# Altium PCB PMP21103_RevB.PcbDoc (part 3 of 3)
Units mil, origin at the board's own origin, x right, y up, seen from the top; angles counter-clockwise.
Board outline 3500 x 4000 mil, 4 copper layers (Top Layer, Signal Layer 1, Signal Layer 2, Bottom Layer), stack 61.2 mil thick; 194 components, 123 nets, 630 pads, 189 vias.
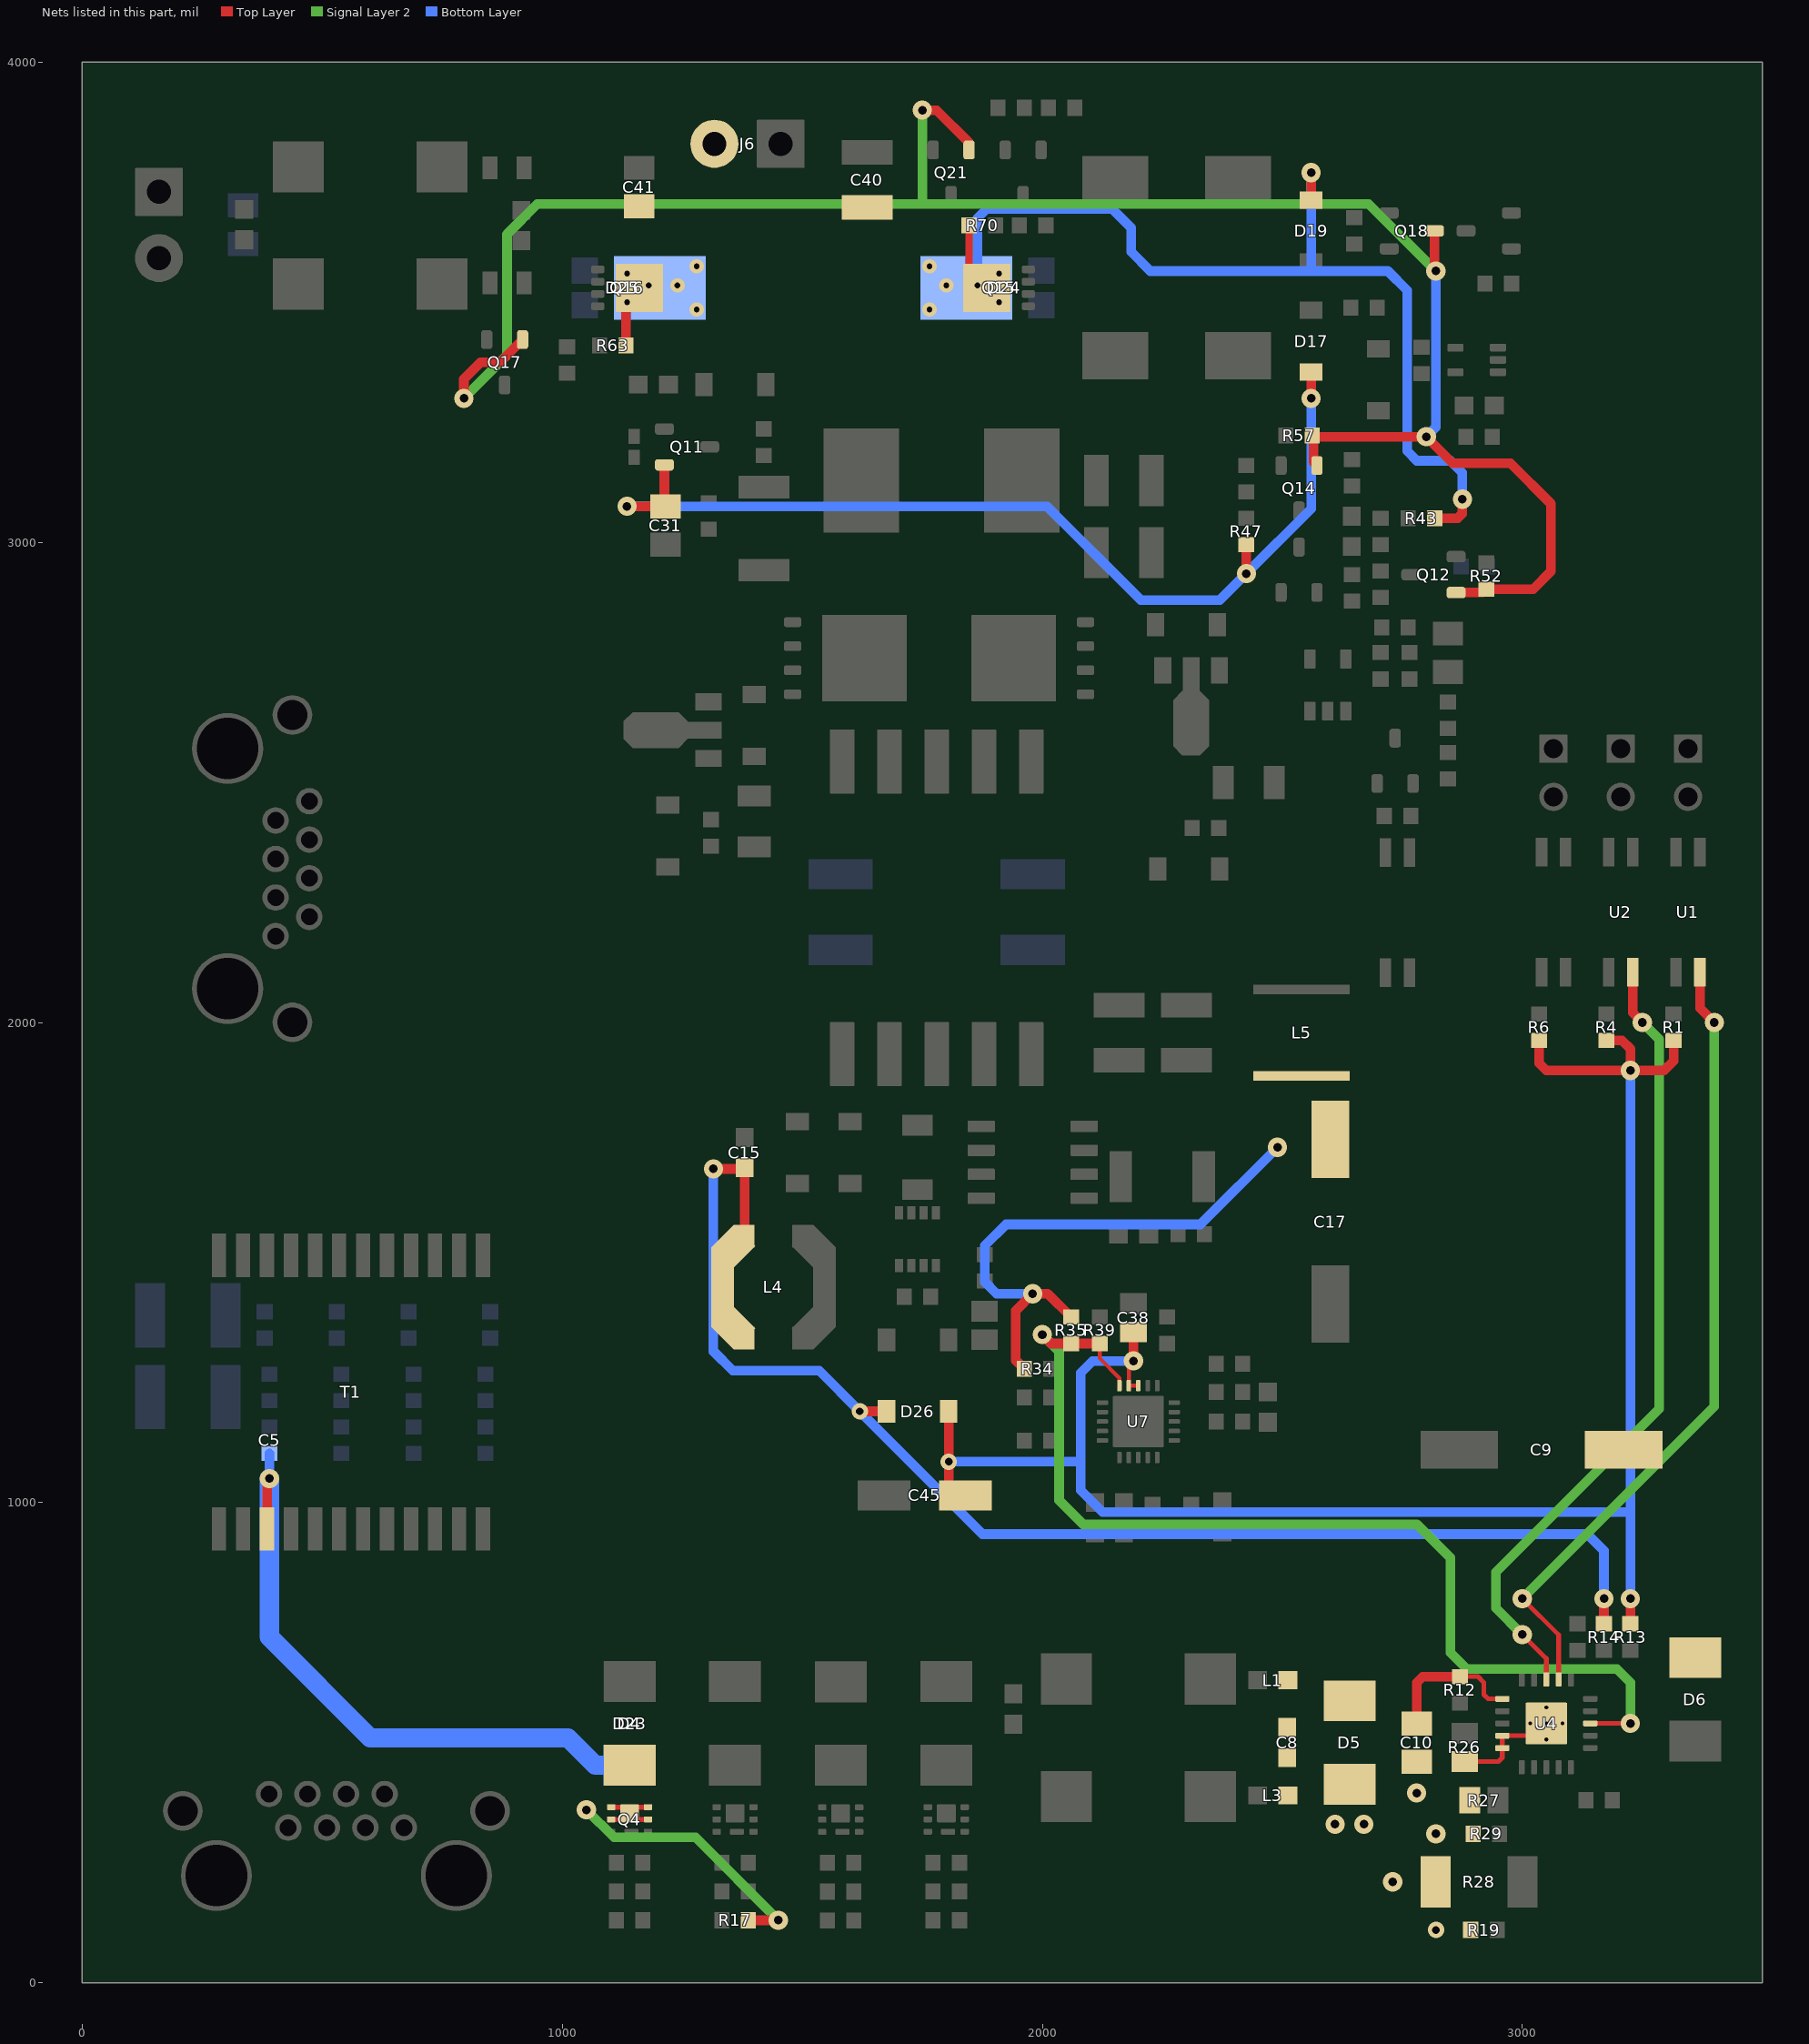
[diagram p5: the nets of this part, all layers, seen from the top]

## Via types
v1: diameter 40, hole 18, Top Layer to Bottom Layer, 163 vias
v2: diameter 30, hole 12, Top Layer to Bottom Layer, 12 vias
v3: diameter 19.68, hole 7.87, Top Layer to Bottom Layer, 10 vias
v4: diameter 34, hole 16, Top Layer to Bottom Layer, 4 vias

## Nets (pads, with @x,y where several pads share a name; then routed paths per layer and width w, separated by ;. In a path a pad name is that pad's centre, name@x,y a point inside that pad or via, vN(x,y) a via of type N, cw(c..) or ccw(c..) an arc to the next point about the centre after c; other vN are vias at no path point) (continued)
PR78: C5.1 D4.2 D23.1 Q4.1 Q4.2 Q4.5 Q4.6 Q4.8 R17.1 T1.15 | length 2028
  Top Layer w10: Q4.2@1101.93,340 Q4.8@1127.52,340 ; Q4.1@1101.93,365.59 Q4.8@1127.52,365.59 ; Q4.8@1140.32,352.8 1153.11,365.59 Q4.6@1178.7,365.59 ; Q4.8@1153.11,340 Q4.5@1178.7,340
  Top Layer w20: T1.15@385,944.96 385,1045 v1(390,1050) ; R17.1@1387.56,130 v1(1450,130)
  Signal Layer 2 w20: v1(1050.32,360) 1107.81,302.5 1277.5,302.5 v1(1450,130)
  Bottom Layer w20: v1(390,1050) C5.1@390,1102.44
  Bottom Layer w40: v1(390,1050) 390,720 600,510 1011.73,510 1068.74,452.99 D23.1@1140,452.99
SS: R35.1 R39.2 U4.13 U7.15 | length 2223.3
  Top Layer w8: R39.2@2120,1331.18 2120,1300 2160.63,1259.37 U7.15@2160.63,1243.54
  Top Layer w10: U4.13@3141.54,540 v1(3225,540)
  Top Layer w20: v1(2000,1350) 2018.82,1331.18 R35.1@2060,1331.18 R39.2@2120,1331.18
  Signal Layer 2 w20: v1(2000,1350) 2035,1315 2035,1005 2085,955 2780,955 2850,885 2850,687.56 2884.29,653.27 3196.73,653.27 3225,625 v1(3225,540)
TPH: U2.2 U4.18 | length 1680.6
  Top Layer w10: v1(3000,725) 3050,675 U4.18@3050,631.54
  Top Layer w20: U2.2@3230,2105 3230,2020 v1(3250,2000)
  Signal Layer 2 w20: v1(3000,725) 2945,780 2945,855 3285,1195 3285,1965 v1(3250,2000)
TPL: U1.2 U4.17 | length 1682.9
  Top Layer w10: v1(3000,800) 3075.59,724.41 U4.17@3075.59,631.54
  Top Layer w20: U1.2@3370,2105 3370,2030 v1(3400,2000)
  Signal Layer 2 w20: v1(3000,800) 3400,1200 v1(3400,2000)
VCIN: C15.2 D26.2 L4.1 R14.2 | length 2818.3
  Top Layer w20: v1(1315,1695) C15.2@1377.76,1695 ; L4.1@1380,1556.55 C15.2@1380,1697.24 ; v4(1620,1190) D26.2@1675.53,1190 ; R14.2@3170,747.56 v1(3170,800)
  Bottom Layer w20: v1(1315,1695) 1315,1315 1355,1275 1535,1275 v4(1620,1190) 1875.71,934.29 3135.71,934.29 3170,900 v1(3170,800)
VCOUT: C38.1 C45.1 D26.1 R1.1 R4.1 R6.1 R13.2 U7.13 U7.14 | length 3785.4
  Top Layer w8: v1(2190,1295) 2180.31,1285.31 U7.14@2180.31,1243.54 U7.13@2200,1243.54
  Top Layer w20: D26.1@1804.47,1190 1805,1189.47 v4(1805,1085) 1805,1020 1834.65,1020 C45.1@1839.65,1015 ; v1(2190,1295) C38.1@2190,1355.47 ; R6.1@3035,1962.44 3035,1915 3050,1900 v1(3225,1900) ; R4.1@3175,1962.44 3207.56,1962.44 3225,1945 v1(3225,1900) ; R13.2@3225,747.56 v1(3225,800) ; R1.1@3315,1962.44 3315,1920 3295,1900 v1(3225,1900)
  Bottom Layer w20: v4(1805,1085) 2080,1085 ; v1(2190,1295) 2105,1295 2080,1270 2080,1085 ; v1(3225,800) 3225,980 ; v1(3225,1900) 3225,980 ; 2080,1085 2080,1025.31 2125.31,980 3225,980
VDD: C8.1 C9.1 C10.2 C17.1 D5.1 D6.1 L1.2 L5.1 R12.2 R34.2 R35.2 U4.1 | length 1460.9
  Top Layer w10: R12.2@2870,637.56 2907.44,637.56 2920,625 2920,600 2928.82,591.18 U4.1@2958.46,591.18
  Top Layer w20: R34.2@1962.44,1278.74 1945,1296.18 1945,1400 v1(1980,1435) 2011.3,1435 R35.2@2060,1386.3 ; C10.2@2780,540 2780,625 2792.56,637.56 R12.2@2870,637.56
  Bottom Layer w20: v1(1980,1435) 1905,1435 1880,1460 1880,1535 1924.41,1579.41 2329.41,1579.41 v1(2490,1740)
VOUT: C40.1 C41.1 D19.2 D24.3 D25.3 J6.2 Q15.5 Q15.6 Q15.7 Q15.8 Q15.9@1884.61,3530 Q16.5 Q16.6 Q16.7 Q16.8 Q16.9@1160.39,3530 R43.2 R63.2 R70.1 | length 2257.5
  Top Layer w15: R70.1@1847.44,3660 1847.44,3567.17 Q15.9@1884.61,3530
  Top Layer w20: R63.2@1132.56,3410 Q16.9@1132.56,3502.17 ; D19.2@2560,3713.21 v1(2560,3770) ; R43.2@2817.56,3050 2865,3050 2875,3060 v1(2875,3090)
  Top Layer w35: Q16.9@1160,3530.39 Q16.9@1160.39,3530
  Bottom Layer w20: v2(1865,3535) 1865,3675 1884.21,3694.21 2145.79,3694.21 2185,3655 2185,3605 2225,3565 2560,3565 ; v1(2560,3770) 2560,3565 ; v1(2875,3090) 2875,3145 2850,3170 2780,3170 2760,3190 2760,3525 2720,3565 2560,3565
  other v2: 1280,3485 1765,3485 1135,3500 1910,3500 1180,3535 1240,3535 1800,3535 1135,3560 1910,3560 1280,3575 1765,3575
VSB: C31.1 D17.2 Q11.2 R47.2 | length 2092.3
  Top Layer w20: v1(1135,3075) C31.1@1210.51,3075 ; Q11.2@1210,3158.58 Q11.2@1212.76,3161.34 C31.1@1212.76,3077.24 ; v1(2425,2935) R47.2@2425,2995.01 ; v1(2560,3300) D17.2@2560,3354.27
  Bottom Layer w20: v1(1135,3075) 2010,3075 2205,2880 2370,2880 v1(2425,2935) 2560,3070 v1(2560,3300)
VSS: C8.2 C10.1 D5.2 L3.2 R19.2 R26.1 R27.1 R28.1 R29.1 U4.4 U4.5 U4.21@3050,540 | length 229.6
  Top Layer w10: R26.1@2880,460.47 2950.08,460.47 2958.46,468.86 U4.5@2958.46,488.82 U4.4@2958.46,514.41 3024.41,514.41 v3(3050,540)
  other v1: 2730,210 2820,310 2610,330 2670,330 2780,395
  other v3: 3050,506.54 3016.54,540 3083.46,540 3050,573.46
  other v4: 2820,110
VT: Q12.1 Q14.1 Q17.1 Q18.3 Q21.1 R52.2 R57.2 | length 4340.7
  Top Layer w20: v1(795,3300) 795,3340 830,3375 870.16,3375 Q17.1@917.4,3422.24 ; v1(1750,3900) 1780,3900 1847.4,3832.6 Q21.1@1847.4,3817.24 ; Q14.1@2572.21,3160.01 2565.13,3167.09 2565.13,3220 v1(2800,3220) 2855,3165 2975,3165 3060,3080 3060,2940 3022.44,2902.44 R52.2@2925,2902.44 2917.92,2895.36 Q12.1@2862.05,2895.36 ; Q18.3@2817.24,3648.74 2817.24,3567.76 v1(2820,3565)
  Signal Layer 2 w20: v1(795,3300) 885,3390 885,3641.65 948.35,3705 1750,3705 ; v1(1750,3900) 1750,3705 ; v1(2820,3565) 2680,3705 1750,3705
  Bottom Layer w20: v1(2800,3220) 2820,3240 v1(2820,3565)
pads on no net: Q1.0 Q2.0 Q3.0 Q4.0 Q5.9@1575.04,2701.65 Q5.9@1575.04,2758.74 Q5.9@1575.04,2815.83 Q5.9@1611.65,2758.74 Q5.9@1645.12,2701.65 Q5.9@1645.12,2758.74 Q5.9@1645.12,2815.83 Q10.9@1924.88,2701.65 Q10.9@1924.88,2758.74 Q10.9@1924.88,2815.83 Q10.9@1958.35,2758.74 Q10.9@1994.96,2701.65 Q10.9@1994.96,2758.74 Q10.9@1994.96,2815.83 Q15.9@1863.74,3491.61 Q15.9@1863.74,3517.2 Q15.9@1863.74,3542.8 Q15.9@1863.74,3568.39 Q15.9@1882.54,3503.92 Q15.9@1882.54,3556.08 Q15.9@1897.11,3530 Q15.9@1918.17,3503.92 Q15.9@1918.17,3556.08 Q16.9@1126.83,3503.92 Q16.9@1126.83,3556.08 Q16.9@1147.89,3530 Q16.9@1162.46,3503.92 Q16.9@1162.46,3556.08 Q16.9@1181.26,3491.61 Q16.9@1181.26,3517.2 Q16.9@1181.26,3542.8 Q16.9@1181.26,3568.39 T2.3 T2.8 U4.20 U4.21@3026.77,516.77 U4.21@3026.77,563.23 U4.21@3073.23,516.77 U4.21@3073.23,563.23 U6.1 U6.2 U7.4 U7.17 U7.18 U7.19 U7.21@2172.64,1141.38 U7.21@2172.64,1196.1 U7.21@2227.36,1141.38 U7.21@2227.36,1196.1 U8.1

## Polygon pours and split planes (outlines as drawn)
NetD7_1 on Top Layer "TOP_LAYER_NETD7_1_P110" (solid, remove dead copper, pour order 110): 1465,1300 1465,1715 1630,1715 1630,1595 1590,1595 1590,1300
VCIN on Top Layer "TOP_LAYER_VCIN_P111" (solid, remove dead copper, pour order 111): 1400,1300 1400,1715 1290,1715 1290,1300
NetC21_2 on Top Layer "TOP_LAYER_NETC21_2_P112" (solid, remove dead copper, pour order 112): 2405,2670 2405,2460 2215,2460 2215,2670
NetC26_1 on Top Layer "TOP_LAYER_NETC26_1_P108" (solid, remove dead copper, pour order 108): 1245,2705 1050,2705 1050,2515 1245,2515
PR45 on Top Layer "TOP_LAYER_PR45_P090" (solid, pour order 90): 1380,330 1340,330 1340,405 1295,405 1295,335 1245,335 1245,500 1420,500 1420,405 1380,405
PR78 on Top Layer "TOP_LAYER_PR78_P089" (solid, pour order 89): 1160,330 1120,330 1120,405 1075,405 1075,335 1025,335 1025,500 1200,500 1200,405 1160,405
NetC7_1 on Top Layer "TOP_LAYER_NETC7_1_P088" (solid, pour order 88): 2110,580 1060,580 1060,690 2110,690
VDD on Top Layer "TOP_LAYER_VDD_P091" (solid, pour order 91): 3450,625 3290,625 3290,850 2815,850 2815,520 2490,520 2490,1000 3100,1000 3100,1650 2435,1650 2435,1950 2800,1950 2800,1800 3450,1800
VSS on Top Layer "TOP_LAYER_VSS_P092" (solid, pour order 92): 2915,480 2490,480 2490,50 2915,50
NetC16_2 on Top Layer "TOP_LAYER_NETC16_2_P094" (solid, pour order 94): 2645,2010 2050,2010 2050,1865 1950,1865 1950,2090 2645,2090
NetC25_1 on Top Layer "TOP_LAYER_NETC25_1_P095" (solid, pour order 95): 1905,2005 1905,1840 1950,1840 1950,1600 1830,1600 1830,1720 1705,1720 1705,1840 1830,1840 1830,2005
NetQ8_1 on Top Layer "TOP_LAYER_NETQ8_1_P096" (solid, pour order 96): 2050,1600 2050,1750 2215,1750 2215,1600
NetC21_2 on Top Layer "TOP_LAYER_NETC21_2_P097" (solid, pour order 97): 1720,2475 1720,3375 1540,3375 1540,2475
NetC26_1 on Top Layer "TOP_LAYER_NETC26_1_P098" (solid, pour order 98): 2030,2475 1850,2475 1850,2860 2030,2860
12V_POE on Top Layer "TOP_LAYER_12V_POE_P099" (solid, pour order 99): 2050,3455 1955,3455 1955,3550 2050,3550 2050,3850 2250,3850 2250,3220 2150,3220 2150,2885 1850,2885 1850,3400 2050,3400
VOUT on Top Layer "TOP_LAYER_VOUT_P100" (solid, pour order 100): 1110,3645 1110,3725 1250,3725 1250,3900 1370,3900 1370,3725 1700,3725 1700,3605 1935,3605 1935,3455 1110,3455
12V_AUX on Top Layer "TOP_LAYER_12V_AUX_P101" (solid, pour order 101): 895,3470 1035,3470 1035,3510 1090,3510 1090,3645 895,3645
PGND on Top Layer "TOP_LAYER_PGND_P124" (solid, remove dead copper, pour order 124): 1850,800 1750,900 1500.96,900 1200,1200.96 1200,2185 3450,2185 3450,50 3130,50 3130,620 2490,620 2490,800
GND on Top Layer "TOP_LAYER_GND_P120" (solid, remove dead copper, pour order 120): 3450,3950 3450,2275 1050,2275 1050,2900 700,3250 700,3450 895,3450 895,3950
BSVG on Top Layer "TOP_LAYER_BSVG_P132" (solid, remove dead copper, pour order 132): 950,400 950,60 60,60 60,2750 950,2750
PR36 on Top Layer "TOP_LAYER_PR36_P103" (solid, pour order 103): 1600,335 1560,335 1560,405 1515,405 1515,335 1465,335 1465,500 1640,500 1640,405 1600,405
PR12 on Top Layer "TOP_LAYER_PR12_P106" (solid, pour order 106): 1820,335 1780,335 1780,400.24 1779.76,400 1735,400 1735,335 1685,335 1685,500 1860,500 1860,400 1820,400
NetC25_2 on Top Layer "TOP_LAYER_NETC25_2_P104" (solid, pour order 104): 1790,1530 1790,1675 1690,1675 1690,1530
VSS on Bottom Layer "BOTTOM_LAYER_VSS_P093" (solid, pour order 93): 3095,585 3095,50 2490,50 2490,480 2490,585
NetC16_2 on Bottom Layer "BOTTOM_LAYER_NETC16_2_P102" (solid, pour order 102): 2055,2185 2055,2025 1905,2025 1905,2185
BSVG on Bottom Layer "BOTTOM_LAYER_BSVG_P134" (solid, remove dead copper, pour order 134): 950,2750 950,400 950,60 60,60 60,2750
GND on Bottom Layer "BOTTOM_LAYER_GND_P123" (solid, remove dead copper, pour order 123): 3450,3950 3450,2275 1050,2275 1050,2900 700,3250 700,3450 895,3450 895,3950
PGND on Bottom Layer "BOTTOM_LAYER_PGND_P130" (solid, remove dead copper, pour order 130): 1850,800 1749.57,900.43 1500.53,900.43 1200.96,1200 1200,1200 1200,2185 3450,2185 3450,50 3130,50 3130,620 2490,620 2490,800
12V_POE on Bottom Layer "BOTTOM_LAYER_12V_POE_P107" (solid, remove dead copper, pour order 107): 1970,3460 2100,3460 2100,3635 1970,3635
12V_AUX on Bottom Layer "BOTTOM_LAYER_12V_AUX_P105" (solid, remove dead copper, pour order 105): 1085,3455 1085,3645 895,3645 895,3455
VOUT on Bottom Layer "BOTTOM_LAYER_VOUT_P109" (solid, remove dead copper, pour order 109): 1110,3455 1935,3455 1935,3605 1700,3605 1700,3645 1370,3645 1370,3900 1250,3900 1250,3645 1110,3645
NetC7_2 on Bottom Layer "BOTTOM_LAYER_NETC7_2_P115" (solid, remove dead copper, pour order 115): 1060,580 1900,580 1900,690 1060,690
PR78 on Bottom Layer "BOTTOM_LAYER_PR78_P116" (solid, remove dead copper, pour order 116): 1200,500 1200,335 1025,335 1025,500
PR45 on Bottom Layer "BOTTOM_LAYER_PR45_P117" (solid, remove dead copper, pour order 117): 1245,335 1420,335 1420,500 1245,500
PR36 on Bottom Layer "BOTTOM_LAYER_PR36_P118" (solid, remove dead copper, pour order 118): 1640,500 1640,335 1465,335 1465,500
PR12 on Bottom Layer "BOTTOM_LAYER_PR12_P119" (solid, remove dead copper, pour order 119): 1860,500 1685,500 1685,335 1860,335
GND on Signal Layer 1 "SIGNAL_LAYER_1_GND_P121" (solid, pour order 121): 895,3950 895,3450 700,3450 700,3250 1050,2900 1050,2275 3450,2275 3450,3950
PGND on Signal Layer 1 "SIGNAL_LAYER_1_PGND_P126" (solid, pour order 126): 1200,1200.96 1500.53,900.43 1749.57,900.43 1850,800 2490,800 2490,620 3130,620 3130,50 3450,50 3450,2185 1200,2185
VSS on Signal Layer 1 "SIGNAL_LAYER_1_VSS_P114" (solid, remove dead copper, pour order 114): 2490,50 2490,585 3095,585 3095,50
GND on Signal Layer 2 "SIGNAL_LAYER_2_GND_P122" (solid, pour order 122): 1050,2275 1050,2900 700,3250 700,3450 895,3450 895,3950 3450,3950 3450,2275
PGND on Signal Layer 2 "SIGNAL_LAYER_2_PGND_P128" (solid, pour order 128): 1850,800 1749.57,900.43 1500.53,900.43 1200,1200.96 1200,2185 3450,2185 3450,50 3130,50 3130,620 2490,620 2490,800
VSS on Signal Layer 2 "SIGNAL_LAYER_2_VSS_P113" (solid, remove dead copper, pour order 113): 2490,50 2490,585 3095,585 3095,50

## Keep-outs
Keep-Out Layer:
  lines w8: -4,4000 -4,0 ; 0,4004 3500,4004 ; -4,0 ccw(c0,0) 0,-4 ; -4,0 ccw(c0,0) 0,-4 ; 0,-4 3500,-4 ; 3500,-4 ccw(c3500,0) 3504,0 ; 3500,-4 ccw(c3500,0) 3504,0 ; 3500,4004 cw(c3500,4000) 3504,4000 ; 3500,4004 cw(c3500,4000) 3504,4000 ; 3504,0 3504,4000 ; 3.51,3942.93 cw(c7.51,3942.93) 7.51,3946.93 ccw(c7.51,3942.93) 3.51,3942.93
  text ".Layer_Name" at 577,-858.49 h60

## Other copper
Top Layer:
  text ".Layer_Name" at 577,-858.49 h60
Bottom Layer:
  text ".Layer_Name" at 577,-858.49 h60

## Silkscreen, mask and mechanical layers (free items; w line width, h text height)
Top Overlay:
  lines w10: 705,3435 790,3435 845,3490 ; 905,2830 925,2810 1135,2810 1210,2885 1370,2885 ; 950,3280 950,3295 975,3320 ; 990,3115 1120,3115 1135,3130 ; 1075,3275 1075,3375 ; 1280,210 1280,235 1295,250 ; 1515,160 1515,245 1520,250 ; 1535,3635 1735,3635 1760,3660 1810,3660 ; 2075,3205 2075,3225 ; 2110,1280 2130,1280 2165,1315 ; 2785,345 2800,345 2835,380 2835,415 2845,425 ; 2900,2740 2935,2705
  text "-" at 1575,3935 h100
  text "+" at 1160,3930 h100
  text "AUX" at 175,3900 h72.83
  text "-" at 140,3830 h100
  text "VOUT" at 1315,3625 h72.83
  text "+" at 135,3425 h100
  text "'.PRJ_Number'.PCB_Rev-" at 50,3165 h108.27
  text "DATA" at 780,2280 h72.83
  text "POWER + DATA" at 140,730 h72.83
  text ".Layer_Name" at 577,-858.49 h60
Bottom Overlay:
  text ".Layer_Name" at 577,-858.49 h60
Top Paste:
  text ".Layer_Name" at 577,-858.49 h60
Bottom Paste:
  text ".Layer_Name" at 577,-858.49 h60
Top Solder:
  text ".Layer_Name" at 577,-858.49 h60
  text ".Layer_Name" at 577,-858.49 h60
Bottom Solder:
  text ".Layer_Name" at 577,-858.49 h60
Drill Guide:
  text ".Layer_Name" at 577,-858.49 h60
M1 Board Outline:
  the board outline again, w10
  text ".Layer_Name" at 577,-858.49 h60
M2 Board Dimensions:
  rectangle: 125,-400 500,-275
  rectangle: 0,-275 125,-150
  lines w7: 0,-275 1000,-275 ; 125,-400 125,-150 ; 250,-400 250,-150 ; 500,-400 500,-150 ; 750,-400 750,-150 ; 0,-400 0,-150 1000,-150 1000,-400 0,-400
  text ".Layer_Name" at 577,-858.49 h60
M3 3D STEP Top:
  text ".Layer_Name" at 577,-858.49 h60
M4 3D STEP Bottom:
  text ".Layer_Name" at 577,-858.49 h60
M5 Assembly Top:
  lines w10: -292,-930.17 6308,-930.17 ; -292,-726.83 6310,-726.83 ; -292,-523.5 -292,-1133.5 3713,-1133.5 6310,-1133.5 6310,-523.5 -291.5,-523.5 -291.5,-1133.5 1284,-1133.5 ; 2173,-1133.5 2173,-523.5 ; 3440,-726.83 3440,-523.5 ; 4280,-726.83 4280,-523.5 ; 4902,-1140 4902,-937.17
  text "COMPONENTS MARKED 'DNP' SHOULD NOT BE POPULATED." at 1153.5,-318.5 h60
  text "ASSEMBLY VARIANT:" at 1153,-434 h60
  text ".VariantName" at 2189,-434 h60
  text "PCB VIEWED FROM TOP SIDE" at -228.5,-655.67 h60
  text "BOARD #:" at 2248,-655.67 h60
  text ".PRJ_Number" at 2793.5,-655.67 h60
  text "REV:" at 3638,-655.67 h60
  text ".PCB_Rev" at 3929.5,-655.67 h60
  text "SVN REV:" at 4476,-655.67 h60
  text ".VersionControl_RevNumber" at 4982,-655.67 h60
  text "TID #:" at 2248,-859 h60
  text ".TID" at 2793.5,-859 h60
  text "PLOT NAME =" at -228.5,-1064.34 h60
  text ".plot_File_Name" at 577,-1064.34 h60
  text "GENERATED    :" at 2250,-1064.34 h60
  text ".Print_Date" at 3119.5,-1064.34 h60
  text ".Print_Time" at 3848.5,-1064.34 h60
  text "TEXAS INSTRUMENTS" at 5113,-1064.34 h60
M6 Assembly Bottom:
  lines w10: -292.5,-727.33 6309.5,-727.33 ; -290.5,-930.67 6309.5,-930.67 ; 1115.5,-1140.5 1115.5,-937.67 ; 1737.5,-727.33 1737.5,-524 ; 2577.5,-727.33 2577.5,-524 ; 3844.5,-1134 3844.5,-524 ; 4733.5,-1134 6309,-1134 6309,-524 -292.5,-524 -292.5,-1134 2304.5,-1134 6309.5,-1134 6309.5,-524
  text "COMPONENTS MARKED 'DNP' SHOULD NOT BE POPULATED." at 6102,-318 h60
  text ".VariantName" at 5058,-434 h60
  text "ASSEMBLY VARIANT:" at 6097,-434 h60
  text ".VersionControl_RevNumber" at 1035.5,-656.17 h60
  text "SVN REV:" at 1541.5,-656.17 h60
  text ".PCB_Rev" at 2088,-656.17 h60
  text "REV:" at 2379.5,-656.17 h60
  text ".PRJ_Number" at 3224,-656.17 h60
  text "BOARD #:" at 3769.5,-656.17 h60
  text "PCB VIEWED FROM BOTTOM SIDE" at 6246,-656.17 h60
  text ".TID" at 3224,-859.5 h60
  text "TID #:" at 3769.5,-859.5 h60
  text "TEXAS INSTRUMENTS" at 904.5,-1064.84 h60
  text ".Print_Time" at 2169,-1064.84 h60
  text ".Print_Date" at 2898,-1064.84 h60
  text "GENERATED    :" at 3767.5,-1064.84 h60
  text ".plot_File_Name" at 5440.5,-1064.84 h60
  text "PLOT NAME =" at 6246,-1064.84 h60
M9 Title Sheet:
  drawing of 57 lines, arcs and shapes, not listed
  text "1" at 739.84,8036.5 h70
  text "2" at 3235.5,8036.5 h70
  text "3" at 5724.84,8036.5 h70
  text "4" at 8231.51,8036.5 h70
  text "5" at 10730.5,8036.5 h70
  text "6" at 13235.5,8036.5 h70
  text "A" at -416.5,6893.5 h70
  text "A" at 14383.5,6893.5 h70
  text "B" at -416.5,4513.5 h70
  text "B" at 14383.5,4513.5 h70
  text "C" at -416.5,2138.5 h70
  text "C" at 14383.5,2138.5 h70
  text "PROJECT TITLE:" at 11343.5,277.5 h45
  text ".PRJ_Title" at 11393.5,144.17 h70
  text "DESIGNED FOR:" at 11343.5,-23.5 h45
  text ".PRJ_Customer" at 11393.5,-163.5 h70
  text "D" at -416.5,-231.5 h70
  text "D" at 14383.5,-231.5 h70
  text "FILE NAME:" at 11343.5,-323.5 h45
  text ".PCB_File_Name_No_Path" at 11393.5,-443.5 h70
  text "Texas Instruments (TI) and/or its licensors do not warrant the accuracy or completeness of this specification" at 6374,-605.34 h45
  text "ENGINEER:" at 11343.5,-613.5 h45
  text "LAYOUT BY:" at 12848.5,-613.5 h45
  text "or any information contained therein. TI and/or its licensors do not warrant that this design will meet" at 6329.01,-718 h45
  text ".PRJ_Engineer" at 11393.5,-768.49 h70
  text ".PCB_Layout" at 12899,-768.49 h70
  text "the specifications, will be suitable for your application or fit for any particular purpose, or will operate in" at 6329.01,-830.67 h45
  text ".Layer_Name" at 577,-858.49 h60
  text "ALTIUM DESIGNER VERSION:" at 12848.5,-923.5 h45
  text "an implementation. TI and/or its licensors do not warrant that the design is production worthy. You should" at 6329.01,-943.33 h45
  text "completely validate and test your design implementation to confirm the system functionality for your application." at 6374,-1056 h45
  text ".print_Scale" at 11393.5,-1056.83 h70
  text ".Application_BuildNumber" at 12899,-1056.83 h70
  text "1" at 739.84,-1263.5 h70
  text "2" at 3235.5,-1263.5 h70
  text "3" at 5724.84,-1263.5 h70
  text "4" at 8231.51,-1263.5 h70
  text "5" at 10730.5,-1263.5 h70
  text "6" at 13235.5,-1263.5 h70
M10 Fab Notes:
  drawing of 189 lines, arcs and shapes, not listed
  text "DESIGN INFORMATION" at 12382.02,6356.17 h60
  text "MIN. TRACK WIDTH:" at 11737.46,6224.05 h60
  text "8" at 12833.7,6224.05 h60
  text "MIL" at 12988.46,6224.05 h60
  text "MIN. CLEARANCE:" at 11737.46,6099.92 h60
  text "0.2" at 12773.7,6099.93 h60
  text "mm" at 12988.46,6099.92 h60
  text "MIN. VIA PAD SIZE:" at 11737.46,5975.8 h60
  text "24" at 12803.71,5975.8 h60
  text "MIL" at 12988.46,5975.8 h60
  text "0.05mm (2MIL)" at 12432.46,5845.9 h60
  text "MINIMUM ANNULAR RING" at 11408.23,5837.67 h60
  text "EXTERNAL" at 13140.46,5837.67 h60
  text "PER" at 11608.23,5727.55 h60
  text "IPC-D-275 CLASS 2 LEVEL C" at 11828.23,5727.54 h60
  text "MIL, HOLES" at 13316.46,5627.07 h60
  text "+/-" at 12924,5618.48 h60
  text "+/-" at 13778,5618.48 h60
  text "REGISTRATION TOLERANCES:" at 11408.23,5617.42 h60
  text "METAL" at 12608,5617.42 h60
  text "5" at 13184.2,5617.42 h60
  text "3" at 14017.2,5617.42 h60
  text "MIL" at 14133.46,5617.42 h60
  text "HOLE SIZE TOLERANCE (UNLESS OTHERWISE SPECIFIED):" at 11408.23,5519.1 h60
  text "+/-" at 13778,5516.23 h60
  text "3" at 14017.2,5515.17 h60
  text "MIL" at 14133.46,5515.17 h60
  text "MATERIAL:" at 11333.46,5377.52 h60
  text "FR-4 High Tg" at 12319.9,5249 h60
  text "X" at 12175.46,5241.01 h60
  text "FR-408" at 11754.46,5236.49 h60
  text "OTHER" at 13242.46,5236.49 h60
  text "62 MIL (1.6mm) +/-10%" at 12074.56,5093.46 h60
  text "X" at 11954.46,5091.01 h60
  text "THICKNESS:" at 11408.23,5085.24 h60
  text "OTHER" at 13359.46,5085.24 h60
  text "TOLERANCE:" at 11408.23,4946.92 h60
  text "X" at 12256.46,4946.92 h60
  text "ANSI IPC-6012 TYPE 3 CLASS 2" at 12434.48,4946.92 h60
  text "OTHER +/-" at 12434.46,4802.73 h60
  text "BOW & TWIST:" at 11408.23,4657.54 h60
  text "X" at 12256.46,4657.54 h60
  text "ANSI IPC-6012 TYPE 3 CLASS 2" at 12434.48,4657.54 h60
  text "OTHER +/-" at 12434.46,4510.85 h60
  text "DRILLING:" at 11333.46,4380.23 h60
  text "NC_DRILL FILES" at 13094.46,4275.04 h60
  text "REFERENCE:" at 11408.23,4271.1 h60
  text "X" at 12065.46,4271.01 h60
  text "AS SHOWN" at 12243.46,4271.1 h60
  text "X" at 12966.46,4271.1 h60
  text "OTHER" at 13392.46,4128.85 h60
  text "PTH COPPER THICKNESS:" at 11407.91,4125.32 h60
  text "X" at 12547.14,4125.32 h60
  text "20-30 um" at 12675.14,4125.32 h60
  text "BOARD FINISH:" at 11333.46,3977.73 h60
  text "SILKSCREEN:" at 11488.68,3867.6 h60
  text "X" at 12446.46,3867.6 h60
  text "TOP" at 12563.46,3867.6 h60
  text "X" at 12956.46,3867.6 h60
  text "BOTTOM" at 13074.46,3867.6 h60
  text "SILKSCREEN COLOR:" at 11488.68,3712.41 h60
  text "X" at 12445.46,3712.41 h60
  text "WHITE" at 12563.46,3712.41 h60
  text "OTHER" at 13074.46,3712.41 h60
  text "X" at 12576.46,3568.96 h60
  text "GREEN" at 12694.46,3568.96 h60
  text "OTHER" at 13312.46,3568.96 h60
  text "SOLDER RESIST COLOR:" at 11488.68,3562.1 h60
  text "X" at 12576.46,3414.71 h60
  text "MATTE" at 12694.46,3414.71 h60
  text "SEMI-GLOSS" at 13312,3414.07 h60
  text "IMMERSION GOLD (ENIG)" at 12394.46,3241.94 h60
  text "ENEPIG" at 13732,3234.72 h60
  text "SURFACE FINISH:" at 11333.46,3233.72 h60
  text "X" at 12216.46,3233.72 h60
  text "IMM. TIN/SILVER OR EQUIV" at 11663,3096.4 h60
  text "OTHER" at 13094.46,3092.47 h60
  text "ARRAY/PANEL:" at 11333.46,2937.09 h60
  text "X" at 12215,2935 h60
  text "CUT AND TRIM PER M1 BOARD OUTLINE" at 12394.46,2928.87 h60
  text "N.C. ROUTE" at 12394.46,2792.9 h60
  text "V. SCORE" at 13260.46,2792.9 h60
  text "CERTIFICATION:" at 11333.46,2663.77 h60
  text "MATERIALS AND WORKMANSHIP FOR ALL PCBS" at 12058.46,2663.77 h60
  text "TO MEET OR EXCEED THE REQUIREMENTS OF:" at 12058.46,2569.71 h60
  text "X" at 11695.97,2441.08 h60
  text "ANSI IPC-A-600F CLASS ->" at 11823.96,2441.08 h60
  text "X" at 13471.97,2441.08 h60
  text "2" at 13581.96,2441.08 h60
  text "1" at 13266.96,2439.58 h60
  text "3" at 13935.96,2439.58 h60
  text "X" at 12507.97,2293.39 h60
  text "RoHS" at 12635.96,2293.39 h60
  text "OTHER" at 13280.36,2293.39 h60
  text "PER ORDER" at 13677.42,2293.39 h60
  text "ALL BOARDS MUST MEET OR EXCEED UL94-V0 REQUIREMENTS." at 11361,2139.57 h60
  text "PCB MUST BEAR THE UL94V-0 UL REGISTERED MATERIAL ID NUMBER" at 11361,2023.5 h60
  text "ADDITIONAL REQUIREMENTS:" at 11333.46,1854.08 h60
  text "MICROSECTION:" at 11408.23,1746.95 h60
  text "YES" at 12313.96,1746.95 h60
  text "REQUIRED" at 13175.46,1602.62 h60
  text "BARE BOARD ELEC. TEST:" at 11408.23,1599.76 h60
  text "NONE" at 12713.96,1599.76 h60
  text "X" at 13057.46,1599.76 h60
  text "PER ORDER" at 13767.46,1599.76 h60
  text "XX MIL VIAS REQUIRE NON-CONDUCTIVE FILL AND PLANARIZE" at 11576.38,1394.82 h59
  text "XX MIL VIAS REQUIRE CONDUCTIVE FILL AND PLANARIZE" at 11584.38,1290.84 h60
  text "OUTER XX MIL VIAS REQUIRE 50 OHM SINGLE-ENDED IMPEDANCE" at 11583.39,1127.46 h58
  text "LAYER 2 & 3 (INNER LAYERS) XX MIL WIDE, XX MIL SPACE / TRACES REQUIRE 100 OHM DIFFERENTIAL IMPEDANCE" at 11575.39,891.74 h60
  text ".Layer_Name" at 577,-858.49 h60
M11 Gerber Information:
  lines w10: -292,-930.17 6308,-930.17 ; -292,-726.83 6310,-726.83 ; -292,-523.5 -292,-1133.5 3713,-1133.5 6310,-1133.5 6310,-523.5 -291.5,-523.5 -291.5,-1133.5 1284,-1133.5 ; 2173,-1133.5 2173,-523.5 ; 3440,-726.83 3440,-523.5 ; 4280,-726.83 4280,-523.5 ; 4902,-1140 4902,-937.17
  text "ALL ARTWORK VIEWED FROM TOP SIDE" at -228.5,-655.67 h60
  text "BOARD #:" at 2248,-655.67 h60
  text ".PRJ_Number" at 2793.5,-655.67 h60
  text "REV:" at 3638,-655.67 h60
  text ".PCB_Rev" at 3929.5,-655.67 h60
  text "SVN REV:" at 4476,-655.67 h60
  text ".VersionControl_RevNumber" at 4982,-655.67 h60
  text "LAYER NAME =" at -228.5,-858.49 h60
  text "TID #:" at 2248,-859 h60
  text ".TID" at 2793.5,-859 h60
  text "PLOT NAME =" at -228.5,-1064.34 h60
  text ".plot_File_Name" at 577,-1064.34 h60
  text "GENERATED    :" at 2250,-1064.34 h60
  text ".Print_Date" at 3119.5,-1064.34 h60
  text ".Print_Time" at 3848.5,-1064.34 h60
  text "TEXAS INSTRUMENTS" at 5113,-1064.34 h60
M12 Stackup:
  drawing of 295 lines, arcs and shapes, not listed
  text "Layer" at 9755.74,7845 h60
  text "Name" at 10165.66,7845 h60
  text "Material" at 11105.4,7845 h60
  text "Thickness" at 11965.16,7845 h60
  text "Constant" at 12615,7845 h60
  text "Board Layer Stack" at 13184.86,7845 h60
  text "1" at 9755.74,7725 h60
  text "Top Overlay" at 10165.66,7725 h60
  text "2" at 9755.74,7605 h60
  text "Top Solder" at 10165.66,7605 h60
  text "Solder Resist" at 11105.4,7605 h60
  text "0.40mil" at 11965.16,7605 h60
  text "3.5" at 12615,7605 h60
  text "3" at 9755.74,7485 h60
  text "Top Layer" at 10165.66,7485 h60
  text "Copper" at 11105.4,7485 h60
  text "2.80mil" at 11965.16,7485 h60
  text "4" at 9755.74,7365 h60
  text "Dielectric 2" at 10165.66,7365 h60
  text "20.00mil" at 11965.16,7365 h60
  text "4.2" at 12615,7365 h60
  text "5" at 9755.74,7245 h60
  text "Signal Layer 1" at 10165.66,7245 h60
  text "Copper" at 11105.4,7245 h60
  text "2.80mil" at 11965.16,7245 h60
  text "6" at 9755.74,7125 h60
  text "Dielectric1" at 10165.66,7125 h60
  text "FR-4" at 11105.4,7125 h60
  text "10.00mil" at 11965.16,7125 h60
  text "4.2" at 12615,7125 h60
  text "7" at 9755.74,7005 h60
  text "Signal Layer 2" at 10165.66,7005 h60
  text "Copper" at 11105.4,7005 h60
  text "2.80mil" at 11965.16,7005 h60
  text "8" at 9755.74,6885 h60
  text "Dielectric 3" at 10165.66,6885 h60
  text "20.00mil" at 11965.16,6885 h60
  text "4.2" at 12615,6885 h60
  text "9" at 9755.74,6765 h60
  text "Bottom Layer" at 10165.66,6765 h60
  text "Copper" at 11105.4,6765 h60
  text "2.80mil" at 11965.16,6765 h60
  text "10" at 9755.74,6645 h60
  text "Bottom Solder" at 10165.66,6645 h60
  text "Solder Resist" at 11105.4,6645 h60
  text "0.40mil" at 11965.16,6645 h60
  text "3.5" at 12615,6645 h60
  text "11" at 9755.74,6525 h60
  text "Bottom Overlay" at 10165.66,6525 h60
  text ".Layer_Name" at 577,-858.49 h60
M13 Component Bodies Top:
  text ".Layer_Name" at 577,-858.49 h60
M14 Component Bodies Bottom:
  text ".Layer_Name" at 577,-858.49 h60
M15 Courtyards Top:
  text ".Layer_Name" at 577,-858.49 h60
M16 Courtyards Bottom:
  text ".Layer_Name" at 577,-858.49 h60
Drill Drawing:
  circle w10: c3863.72,515.36 r27.63
  lines w10: 3836.09,294.35 3891.34,294.35 3863.72,239.1 3836.09,294.35 ; 3836.09,363.42 3891.34,363.42 3891.34,418.67 3836.09,418.67 3836.09,363.42 ; 3836.09,612.06 3863.72,625.87 3891.34,612.06 3877.53,639.68 3891.34,667.31 3863.72,653.5 3836.09,667.31 3849.9,639.68 3836.09,612.06 ; 3836.09,750.19 3849.9,750.19 3863.72,736.38 3877.53,750.19 3891.34,750.19 3877.53,764 3891.34,777.82 3877.53,777.82 3863.72,791.63 3849.9,777.82 3836.09,777.82 3849.9,764 3836.09,750.19 ; 3836.09,860.7 3836.09,874.51 3849.9,888.32 3836.09,902.14 3836.09,915.95 3849.9,915.95 3863.72,902.14 3877.53,915.95 3891.34,915.95 3891.34,902.14 3877.53,888.32 3891.34,874.51 3891.34,860.7 3877.53,860.7 3863.72,874.51 3849.9,860.7 3836.09,860.7 ; 3836.09,985.02 3891.34,985.02 3891.34,1040.27 3836.09,1040.27 3836.09,985.02 ; 3836.09,1136.96 3863.72,1109.34 3891.34,1136.96 3863.72,1164.59 3836.09,1136.96 ; 3836.09,1247.47 3849.9,1247.47 3849.9,1233.66 3877.53,1233.66 3877.53,1247.47 3891.34,1247.47 3891.34,1275.1 3877.53,1275.1 3877.53,1288.91 3849.9,1288.91 3849.9,1275.1 3836.09,1275.1 3836.09,1247.47 ; 3847.14,996.07 3880.29,996.07 3880.29,1029.22 3847.14,1029.22 3847.14,996.07
  lines w12: 3786,201.8 7017.49,201.8 ; 3786,1320.68 7017.49,1320.68 ; 4123.86,77.48 4123.86,1445 ; 4455.86,77.48 4455.86,1445 ; 5092.43,77.48 5092.43,1445 ; 5351.57,77.48 5351.57,1445 ; 5726.72,77.48 5726.72,1445 ; 6451.05,77.48 6451.05,1445 ; 3786,77.48 7017.49,77.48 7017.49,1445 3786,1445 3786,77.48
  text "Symbol" at 3860.59,1357.98 h72
  text "Quantity" at 4161.16,1357.98 h72
  text "Finished Hole Size" at 4493.16,1357.98 h72
  text "Plated" at 5129.72,1357.98 h72
  text "Hole Type" at 5388.86,1357.98 h72
  text "Drill Layer Pair" at 5764.02,1357.98 h72
  text "Hole Tolerance" at 6488.35,1357.98 h72
  text "10" at 4161.16,1233.66 h60
  text "7.87mil (0.200mm)" at 4493.16,1233.66 h60
  text "PTH" at 5129.72,1233.66 h60
  text "Round" at 5388.86,1233.66 h60
  text "Top Layer - Bottom Layer" at 5764.02,1233.66 h60
  text "12" at 4161.16,1109.34 h60
  text "12.00mil (0.305mm)" at 4493.16,1109.34 h60
  text "PTH" at 5129.72,1109.34 h60
  text "Round" at 5388.86,1109.34 h60
  text "Top Layer - Bottom Layer" at 5764.02,1109.34 h60
  text "4" at 4161.16,985.02 h60
  text "16.00mil (0.406mm)" at 4493.16,985.02 h60
  text "PTH" at 5129.72,985.02 h60
  text "Round" at 5388.86,985.02 h60
  text "Top Layer - Bottom Layer" at 5764.02,985.02 h60
  text "163" at 4161.16,860.7 h60
  text "18.00mil (0.457mm)" at 4493.16,860.7 h60
  text "PTH" at 5129.72,860.7 h60
  text "Round" at 5388.86,860.7 h60
  text "Top Layer - Bottom Layer" at 5764.02,860.7 h60
  text "16" at 4161.16,736.38 h60
  text "35.04mil (0.890mm)" at 4493.16,736.38 h60
  text "PTH" at 5129.72,736.38 h60
  text "Round" at 5388.86,736.38 h60
  text "Top Layer - Bottom Layer" at 5764.02,736.38 h60
  text "6" at 4161.16,612.06 h60
  text "40.00mil (1.016mm)" at 4493.16,612.06 h60
  text "PTH" at 5129.72,612.06 h60
  text "Round" at 5388.86,612.06 h60
  text "Top Layer - Bottom Layer" at 5764.02,612.06 h60
  text "4" at 4161.16,487.74 h60
  text "50.00mil (1.270mm)" at 4493.16,487.74 h60
  text "PTH" at 5129.72,487.74 h60
  text "Round" at 5388.86,487.74 h60
  text "Top Layer - Bottom Layer" at 5764.02,487.74 h60
  text "4" at 4161.16,363.42 h60
  text "61.81mil (1.570mm)" at 4493.16,363.42 h60
  text "PTH" at 5129.72,363.42 h60
  text "Round" at 5388.86,363.42 h60
  text "Top Layer - Bottom Layer" at 5764.02,363.42 h60
  text "4" at 4161.16,239.1 h60
  text "128.00mil (3.251mm)" at 4493.16,239.1 h60
  text "PTH" at 5129.72,239.1 h60
  text "Round" at 5388.86,239.1 h60
  text "Top Layer - Bottom Layer" at 5764.02,239.1 h60
  text "223 Total" at 4161.16,114.78 h60
  text ".Layer_Name" at 577,-858.49 h60
M17 Embedded Cavity:
  text ".Layer_Name" at 577,-858.49 h60
M18 Embedded Assembly:
  text ".Layer_Name" at 577,-858.49 h60
M19 Embedded Keepout:
  text ".Layer_Name" at 577,-858.49 h60

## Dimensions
0,0 to 3500,0 on M2 Board Dimensions
0,0 to 0,4000 on M2 Board Dimensions
0,-400 to 1000,-400 on M2 Board Dimensions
